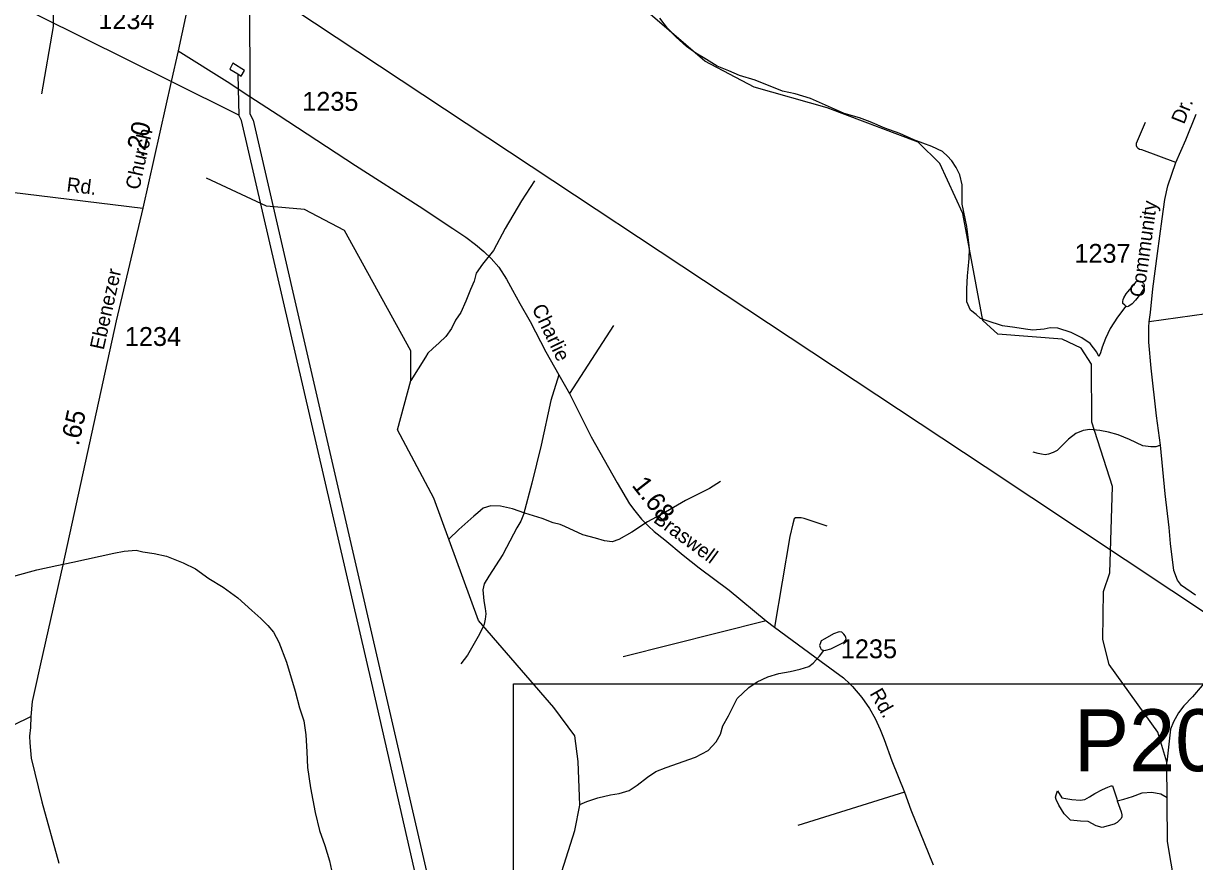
# Model space of a CAD drawing. Extents: x 2206922 to 2357709, y 510027 to 673830.
# Drawn here: x 2263859 to 2271615, y 609576 to 615129 of the extents above; entities that cross this region are included whole.
import ezdxf

# ---------------------------------------------------------------- set-up
doc = ezdxf.new("R2010")
doc.units = 0
for name, color, linetype in [('Exist Hydrographic Creek Single Shore', 7, 'Continuous'), ('Exist Hydrographic Misc Water Feature', 7, 'Continuous'), ('Exist Railroad Mainline', 7, 'Continuous'), ('Exist Road Non-System Type 51', 7, 'Continuous'), ('Exist Road Secondary Mileage Hundredths English Label', 7, 'Continuous'), ('Exist Road Secondary Structure Pipe Number Label', 7, 'Continuous'), ('Exist Road Secondary Type 51 Attributed', 7, 'Continuous'), ('Exist Road Secondary Type 51 Label', 7, 'Continuous'), ('Exist Road Secondary Type 51 Number Label', 7, 'Continuous'), ('Exist Utilities Electrical Transmission Line', 7, 'Continuous'), ('Map Preparation Inset Cut Line', 7, 'Continuous')]:
    doc.layers.add(name, color=color, linetype=linetype)

msp = doc.modelspace()

# ---------------------------------------------------------------- linework, layer by layer
at = {"layer": 'Exist Hydrographic Creek Single Shore'}
msp.add_lwpolyline([(2271790.5, 608262.5), (2271585.4, 608821), (2271435.5, 609709.5), (2271430.4, 610234.3), (2271370.5, 610432.4), (2271049.4, 610881.6), (2271006.6, 611046.4), (2271011.5, 611364.5), (2271052.5, 611488.2), (2271071.6, 612061.8), (2270934.4, 612487.7), (2270931.5, 612871.5), (2270863.4, 612977.8), (2270737.5, 613036.1), (2270312.5, 613070.9), (2270211.4, 613161.5), (2270080.6, 613869.3), (2269927.4, 614200.4), (2269784.5, 614341), (2269182.4, 614569.7), (2268698.5, 614707.4), (2268371.4, 614878.1), (2268010.4, 615190.4)], dxfattribs=at)
at = {"layer": 'Exist Hydrographic Misc Water Feature'}
for points in [[(2263981.7, 614661.5), (2264057.9, 615109.3), (2264064.6, 615583.6), (2264421.3, 616092.6), (2264568.8, 616428.6), (2264601.5, 616460.6)], [(2269949.1, 614275.7), (2269945, 614279.5), (2269874.9, 614312.8), (2269756.6, 614357.8), (2269662.3, 614398.8), (2269564, 614433.9), (2269465.8, 614477.1), (2269395.7, 614502.2), (2269293.4, 614531.4), (2269170.7, 614586), (2269070.7, 614631.1), (2268970, 614662.1), (2268885.7, 614679.2), (2268705.7, 614751.8), (2268601.1, 614784.6), (2268531.2, 614813.8), (2268452.6, 614845.1), (2268381.9, 614890.6), (2268312, 614932), (2268249.4, 614975.1), (2268181, 615036.5), (2268124.6, 615098.1), (2268073.7, 615163.4)], [(2270981.4, 612922.1), (2270967.2, 612951.8), (2270922.9, 613007.6), (2270868.4, 613045), (2270798.2, 613080.3), (2270709.5, 613109.5), (2270657.8, 613112.8), (2270617.8, 613102.6), (2270544, 613095.9), (2270496, 613103.5), (2270424, 613114.8), (2270342, 613125.9), (2270241.7, 613158.9), (2270197.6, 613174.5), (2270167.5, 613200.1), (2270131.2, 613229.9), (2270106.6, 613283.5), (2270106.2, 613329.7), (2270107.6, 613369.7), (2270110.9, 613455.6), (2270114.4, 613499.7), (2270121.8, 613571.6), (2270125.1, 613635.5), (2270116.4, 613713.5), (2270106, 613783.2), (2270076.5, 613930.8), (2270075.2, 614058.7), (2270060.9, 614124.6), (2270036.3, 614174.5), (2270008, 614218.1), (2269977.4, 614251.9), (2269949.1, 614275.7)], [(2267366.5, 609329.6), (2267511.5, 609782.5), (2267543.4, 609949.2), (2267532.4, 610238), (2267511.2, 610408.8), (2267370.9, 610597.2), (2266872.4, 611173.6), (2266577, 611982.8), (2266337.3, 612436.6), (2266425.6, 612762.4), (2266424.5, 612959.6), (2265986.1, 613756.4), (2265720.3, 613896.8), (2265469.1, 613918.9), (2265070.3, 614103.7)], [(2267242.4, 614086.2), (2267157.9, 613953.4), (2267049.7, 613770.6), (2266973, 613623.9), (2266900, 613533.2), (2266858.2, 613473), (2266843.2, 613420.9), (2266819.2, 613366.5), (2266788.4, 613288.4), (2266755.2, 613213.9), (2266721.4, 613161.9), (2266694.1, 613107.6), (2266656.4, 613055.2), (2266612.9, 613012.7), (2266571.1, 612974.4), (2266537.7, 612944.2), (2266521.6, 612917.6), (2266425.6, 612762.4)], [(2271160.2, 613255.7), (2271152.2, 613261.4), (2271140.1, 613273.3), (2271140.1, 613285.5), (2271141.5, 613299.5), (2271145.6, 613311.4), (2271161.4, 613337.4), (2271173.1, 613351.4), (2271209.2, 613393.9), (2271218.8, 613406.2), (2271230.5, 613418.2), (2271246.7, 613420.3), (2271256.9, 613418.3), (2271267, 613414.4), (2271276.6, 613406.4), (2271280.5, 613396.5), (2271281.1, 613384.7), (2271279.1, 613372.4), (2271255.7, 613336.6), (2271223.7, 613296), (2271202, 613271.7), (2271180.3, 613255.9), (2271174.3, 613253.6), (2271167.9, 613251.7), (2271160.2, 613255.7)], [(2271160.2, 613255.7), (2271105.2, 613183.2), (2271056, 613106.8), (2271024, 613040.6), (2271003.1, 612984.1), (2270991.4, 612946.1), (2270981.4, 612922.1)], [(2268474.4, 612093), (2268403, 612048.2), (2268244.1, 611968.8), (2268110.6, 611891.6), (2267991.3, 611826.4), (2267888.1, 611757.6), (2267802.6, 611708.9), (2267756.9, 611694.3), (2267706.7, 611699.8), (2267648.4, 611717.5), (2267562.7, 611740.5), (2267443.8, 611795.4), (2267413.9, 611808.8), (2267367.7, 611820.6), (2267293.7, 611848), (2267179.1, 611884.7), (2267096.8, 611913.8), (2267018.9, 611931.2), (2266954.9, 611932.7), (2266902.9, 611916.2), (2266867.4, 611885.9), (2266842, 611863.8), (2266742.3, 611776.6), (2266676, 611711.6)], [(2263503.9, 611366.5), (2263571.8, 611391.1), (2263665.3, 611424), (2263810.9, 611471.5), (2263948.5, 611508.7), (2264080.3, 611537.9), (2264186.1, 611560.5), (2264458.8, 611619.2), (2264526.9, 611632), (2264606.7, 611638.6)], [(2264606.7, 611638.6), (2264648.9, 611629), (2264724.8, 611617.6), (2264805.4, 611598.5), (2264917.1, 611555.7), (2264997.9, 611514.4), (2265086.3, 611451.2), (2265182.7, 611394.1), (2265279.7, 611323.1), (2265372.2, 611238.2), (2265430.8, 611186.7), (2265477.3, 611139.2), (2265515.5, 611095.7), (2265549.9, 611029.7), (2265601.4, 610896.2), (2265659.2, 610705), (2265688.1, 610593.5), (2265716.8, 610507.7), (2265729.6, 610415.8), (2265736.9, 610301.9), (2265740, 610198), (2265759.1, 610064.2), (2265790.5, 609900.9), (2265819.4, 609781), (2265854.6, 609681.5), (2265885.6, 609581.6), (2265912.7, 609457.9)], [(2272292.9, 611223.1), (2272199.6, 611186.5), (2272165.3, 611180.3), (2272109.3, 611185.5), (2272055.2, 611196.9), (2272002.9, 611202.7), (2271963.3, 611200.2), (2271911.7, 611177.6), (2271871.5, 611153.6), (2271847.9, 611119), (2271824.3, 611084.9), (2271809.1, 611018.7), (2271801.6, 610952.8), (2271768.5, 610884.5), (2271703.1, 610797.8), (2271664, 610741.6), (2271600, 610666.9), (2271542.8, 610606.6), (2271507.5, 610560.4), (2271475.7, 610501.9), (2271454.6, 610453.6), (2271430.4, 610234.3)], [(2269160.5, 610973.8), (2269172.8, 610976), (2269206.4, 610986.3), (2269254.4, 611008.7), (2269294.4, 611029), (2269304, 611041.3), (2269307.7, 611051.3), (2269306.1, 611061.3), (2269301.8, 611071.3), (2269291.7, 611082.9), (2269279.4, 611094.9), (2269261.4, 611098.9), (2269223.6, 611084.3), (2269166, 611052), (2269142.2, 611037.7), (2269136.5, 611025.6), (2269130.6, 611007.5), (2269136.9, 610989.5), (2269142.9, 610981.7), (2269154.5, 610975.9), (2269160.5, 610973.8)], [(2267544.2, 609952.9), (2267589, 609973.7), (2267662.8, 609998.3), (2267746.4, 610018.9), (2267804.5, 610027.6), (2267870.1, 610046.1), (2267923.8, 610082.6), (2267991.3, 610135.3), (2268047.1, 610171.9), (2268114.7, 610198.6), (2268309.9, 610268.1), (2268393.6, 610311.1), (2268446.7, 610369.6), (2268476.2, 610419.9), (2268490, 610475.8), (2268527.3, 610542), (2268556.6, 610598.4), (2268585.9, 610656.8), (2268663.4, 610729.5), (2268717, 610765.6), (2268788.3, 610800.7), (2268860.5, 610821), (2268936.2, 610836), (2269002, 610850.4), (2269059.8, 610868.9), (2269089.5, 610891.2), (2269131.2, 610937.6), (2269160.5, 610973.8)], [(2271102.9, 609978.6), (2271127.8, 609905.1), (2271133.7, 609885.1), (2271133.9, 609872.9), (2271128.2, 609861.2), (2271102.3, 609834.7), (2271082.4, 609824.7), (2271002, 609802.6), (2270963.9, 609812.2), (2270910.4, 609840.9), (2270859.2, 609843.9), (2270792.6, 609850.2), (2270751.4, 609891.5), (2270716.5, 609948.6), (2270697.5, 609986.7), (2270694.3, 610002.6), (2270697.5, 610018.4), (2270707, 610043.8), (2270734.9, 609999.2), (2270802.2, 609986.7), (2270856.1, 609983.5), (2270887.8, 609986.7), (2270919.5, 610005.7), (2270954.4, 610027.9), (2271005.1, 610053.3), (2271040, 610069.2), (2271062.2, 610078.7), (2271070.3, 610078.4), (2271099.1, 609992.6), (2271102.9, 609978.6)], [(2271102.9, 609978.6), (2271145.2, 609989.2), (2271204.7, 610007.4), (2271266.6, 610032.2), (2271332.6, 610034.8), (2271390.4, 610025.3), (2271432.7, 610001.1)]]:
    msp.add_lwpolyline(points, dxfattribs=at)
at = {"layer": 'Exist Railroad Mainline'}
msp.add_lwpolyline([(2277075.8, 607647), (2275362.6, 608781.5), (2275266.2, 608845.4), (2273928.2, 609731.4), (2272391.5, 610753.3), (2270229, 612191.5), (2265356.3, 615416.5), (2265047.6, 615620.9), (2265047, 615621.2)], dxfattribs=at)
at = {"layer": 'Exist Road Non-System Type 51'}
for p, q in [((2271864.9, 613228.8), (2271313.5, 613151.1)), ((2267766.2, 613126.8), (2267475, 612676.3)), ((2268777.6, 611171.3), (2267830.1, 610931.5)), ((2269693.7, 610034.7), (2268987.7, 609814.7))]:
    msp.add_line(p, q, dxfattribs=at)
for points in [[(2271491.5, 614208.1), (2271264.8, 614290.1), (2271250.7, 614294), (2271240.6, 614299.8), (2271234.6, 614307.7), (2271230.4, 614317.8), (2271230.4, 614335.8), (2271289, 614474.1)], [(2267404.8, 612800.4), (2267352.4, 612630.2), (2267287.3, 612334.9), (2267226.3, 612083.1), (2267169.7, 611874.8), (2267153, 611831.3), (2267126.1, 611787.3), (2267104.9, 611744.3), (2267034.2, 611609.6), (2266940.4, 611467.1), (2266911.1, 611415.8), (2266901.3, 611376.7), (2266908.7, 611303.3), (2266916, 611252), (2266920.1, 611216.9), (2266916.3, 611180.8), (2266910.7, 611148.7), (2266896.9, 611118.6), (2266869.4, 611066.3), (2266798.7, 610944), (2266754.8, 610885.3)], [(2271388.5, 612335), (2271357.3, 612323.9), (2271325.3, 612323.6), (2271271.2, 612331.1), (2271182.9, 612372.2), (2271108.6, 612403.5), (2271044.4, 612420.8), (2270986.4, 612432.4), (2270920.3, 612437.8), (2270876.4, 612431.4), (2270828.7, 612412.8), (2270779.1, 612374.4), (2270703.8, 612299.8), (2270677.9, 612285.5), (2270648, 612275.3), (2270626.1, 612271), (2270600, 612274.9), (2270578, 612278.6), (2270546.1, 612288.4)], [(2269180.7, 611797.1), (2269148.9, 611809.3), (2269109.8, 611821.5), (2269069, 611834.6), (2269028.9, 611848.4), (2269009.7, 611853.3), (2268987.7, 611853.3), (2268973, 611853.3), (2268963.2, 611846), (2268953.5, 611814.2), (2268933.9, 611728.7), (2268833.8, 611129.8)]]:
    msp.add_lwpolyline(points, dxfattribs=at)
at = {"layer": 'Exist Road Secondary Type 51 Attributed'}
for points in [[(2265047, 615621.2), (2265037.7, 615604.9), (2264999, 615480.6), (2264883.2, 614948.1)], [(2264883.2, 614948.1), (2264837.6, 614744.3), (2264649.9, 613904)], [(2264883.2, 614948.1), (2265225.9, 614733), (2265281.6, 614696.3), (2265359.1, 614645.1), (2265545.7, 614522.2), (2266058.5, 614187.1), (2266478.9, 613917.3), (2266702.2, 613769.4), (2266789, 613713.5), (2266852.5, 613664.6), (2266908.7, 613618.2), (2266957.5, 613571.7), (2267006.4, 613513.1), (2267057.1, 613434.9), (2267096.8, 613361.5), (2267145.6, 613273.5), (2267213.7, 613154.6), (2267319.4, 612953.7), (2267404.8, 612800.4), (2267475, 612676.3), (2267618.6, 612388.9), (2267791.4, 612084.4), (2267873.7, 611946.2), (2267907.9, 611899.8), (2267951.8, 611843.5), (2267998.3, 611797.1), (2268036.3, 611763), (2268106.8, 611707.8), (2268227.9, 611606.4), (2268332.9, 611520.9), (2268533.6, 611373.8), (2268777.6, 611171.3), (2268833.8, 611129.8), (2269141.8, 610901.8), (2269288.8, 610793.3), (2269330.8, 610753.3), (2269349.2, 610735.9), (2269411.9, 610662.4), (2269462.6, 610591), (2269499.2, 610523.3), (2269533.7, 610449.8), (2269558.4, 610384), (2269609.7, 610242.6), (2269693.7, 610034.7), (2269734.6, 609917.9), (2269884.3, 609553.2)], [(2271619.8, 611340.2), (2271528.9, 611405.5), (2271501.2, 611439.1), (2271476.8, 611503.4), (2271472.5, 611541.5), (2271466, 611593.4), (2271455.2, 611683.2), (2271446.2, 611789.1), (2271420.1, 612012.7), (2271388.5, 612335), (2271363.2, 612527.9), (2271326.3, 612845.4), (2271312.8, 613017.2), (2271311.8, 613117.2), (2271313.5, 613151.1), (2271322.9, 613213.1), (2271339.3, 613369.3), (2271369.1, 613605.4), (2271400.9, 613833.5), (2271417.7, 613961.7), (2271436.9, 614051.9), (2271491.5, 614208.1), (2271557.9, 614356.7), (2271626.3, 614527.3)], [(2262673.9, 614015.5), (2262727.8, 614038), (2262789.5, 614058.6), (2262867.3, 614075.2), (2262901, 614081.4), (2262935.1, 614087.8), (2263001, 614094.5), (2263043.1, 614098.8), (2263094.9, 614093.3), (2263135, 614089.7), (2263185.1, 614084.1), (2264649.9, 613904)], [(2264649.9, 613904), (2264473, 613158.6), (2264120.5, 611542.2), (2263972.7, 610885.3), (2263934.4, 610715.1), (2263917, 610636.9), (2263908.3, 610536.5)], [(2263796.2, 610482.7), (2263908.3, 610536.5)], [(2263908.3, 610536.5), (2263905.3, 610464.7), (2263899.3, 610406.4), (2263902.3, 610363), (2263909.8, 610261.3), (2263981.3, 609971.8), (2264093, 609565.1)]]:
    msp.add_lwpolyline(points, dxfattribs=at)
at = {"layer": 'Exist Utilities Electrical Transmission Line'}
for p, q in [((2265356.3, 615416.5), (2265359.1, 614645.1)), ((2265285.8, 614521.7), (2264837.6, 614744.3)), ((2265279.2, 614795.5), (2265281.6, 614696.3)), ((2265281.6, 614696.3), (2265285.8, 614521.7))]:
    msp.add_line(p, q, dxfattribs=at)
for points in [[(2264837.6, 614744.3), (2263390, 615463.5), (2262731.2, 615790)], [(2265279.2, 614795.5), (2265301.4, 614779.7), (2265323, 614816), (2265246.6, 614865.2), (2265225, 614825), (2265279.2, 614795.5)], [(2265359.1, 614645.1), (2265359.4, 614570.4), (2265357.8, 614530.4), (2265380.1, 614488.6), (2266864.6, 608055.8)], [(2266772.5, 608099.9), (2266173.1, 610730), (2265302.1, 614486), (2265285.8, 614521.7)]]:
    msp.add_lwpolyline(points, dxfattribs=at)
at = {"layer": 'Map Preparation Inset Cut Line'}
msp.add_line((2269330.8, 610753.3), (2272391.5, 610753.3), dxfattribs=at)
msp.add_lwpolyline([(2267104.4, 607961.1), (2267104.4, 610753.3), (2269330.8, 610753.3)], dxfattribs=at)

# ---------------------------------------------------------------- texts
at = {"layer": 'Exist Road Secondary Mileage Hundredths English Label'}
for s, rotation, p in [('.20', 77.40403, (2264654.8, 614235.6)), ('.65', 77.69759, (2264224.4, 612325.5)), ('1.68', 308.03101, (2267883.6, 612067.5))]:
    msp.add_text(s, height=125, rotation=rotation, dxfattribs=at).set_placement(p)
at = {"layer": 'Exist Road Secondary Structure Pipe Number Label'}
msp.add_text('P205', height=410.1, dxfattribs=at).set_placement((2270815.6, 610174.8))
at = {"layer": 'Exist Road Secondary Type 51 Label'}
for s, rotation, p in [('Dr.', 68.15168, (2271544.6, 614455.8)), ('Church', 77.40402, (2264625.6, 614021.2)), ('Rd.', 352.99061, (2264141.1, 614016.1)), ('Community', 82.06301, (2271278.3, 613310.6)), ('Ebenezer', 77.48735, (2264390.3, 612961.4)), ('Charlie', 295.79807, (2267223.4, 613242.5)), ('Braswell', 323.64588, (2268025.1, 611829)), ('Rd.', 299.7216, (2269460.1, 610689.8))]:
    msp.add_text(s, height=95, rotation=rotation, dxfattribs=at).set_placement(p)
at = {"layer": 'Exist Road Secondary Type 51 Number Label'}
for s, p in [('1234', (2264355.2, 615090.7)), ('1235', (2265705.4, 614549.8)), ('1237', (2270819, 613542.7)), ('1234', (2264530.8, 612992)), ('1235', (2269272.3, 610922.9))]:
    msp.add_text(s, height=125, dxfattribs=at).set_placement(p)

doc.saveas('drawing.dxf')
